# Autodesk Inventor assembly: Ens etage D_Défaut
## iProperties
Shininess: 64.0
Length Units: 11269
Angle Units: 11279
Time Units: 11290
Mass Units: 11283
Length Display Precision: 3
Angle Display Precision: 2
Compacted: True
Created: 2006-01
Part Number: Ens etage D_Défaut
Document SubType Name: Assembly
Designer: Fricot
Density: 0.0
Volumn: 0.0
Area: 0.0
PropertySet Name: Model Information
Control State: 0
Master: False
Checked Out: False
Author: Fricot
